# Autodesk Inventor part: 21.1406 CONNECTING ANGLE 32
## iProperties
Created: 2007-01
Part Number: 21.1406 CONNECTING ANGLE 32
Material: Steel
Document SubType Name: Modeling
Designer: Andy Moles
Density: 7.85 g/cm^3
Author: Andy Moles
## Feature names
1. Base1
2. Hole1
3. Hole2
